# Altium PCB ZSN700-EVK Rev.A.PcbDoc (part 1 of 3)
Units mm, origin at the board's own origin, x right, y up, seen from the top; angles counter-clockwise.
Board outline 122.05 x 75.06 mm, 2 copper layers (Top Layer, Bottom Layer), stack 0 mm thick; 172 components, 135 nets, 573 pads, 599 vias.
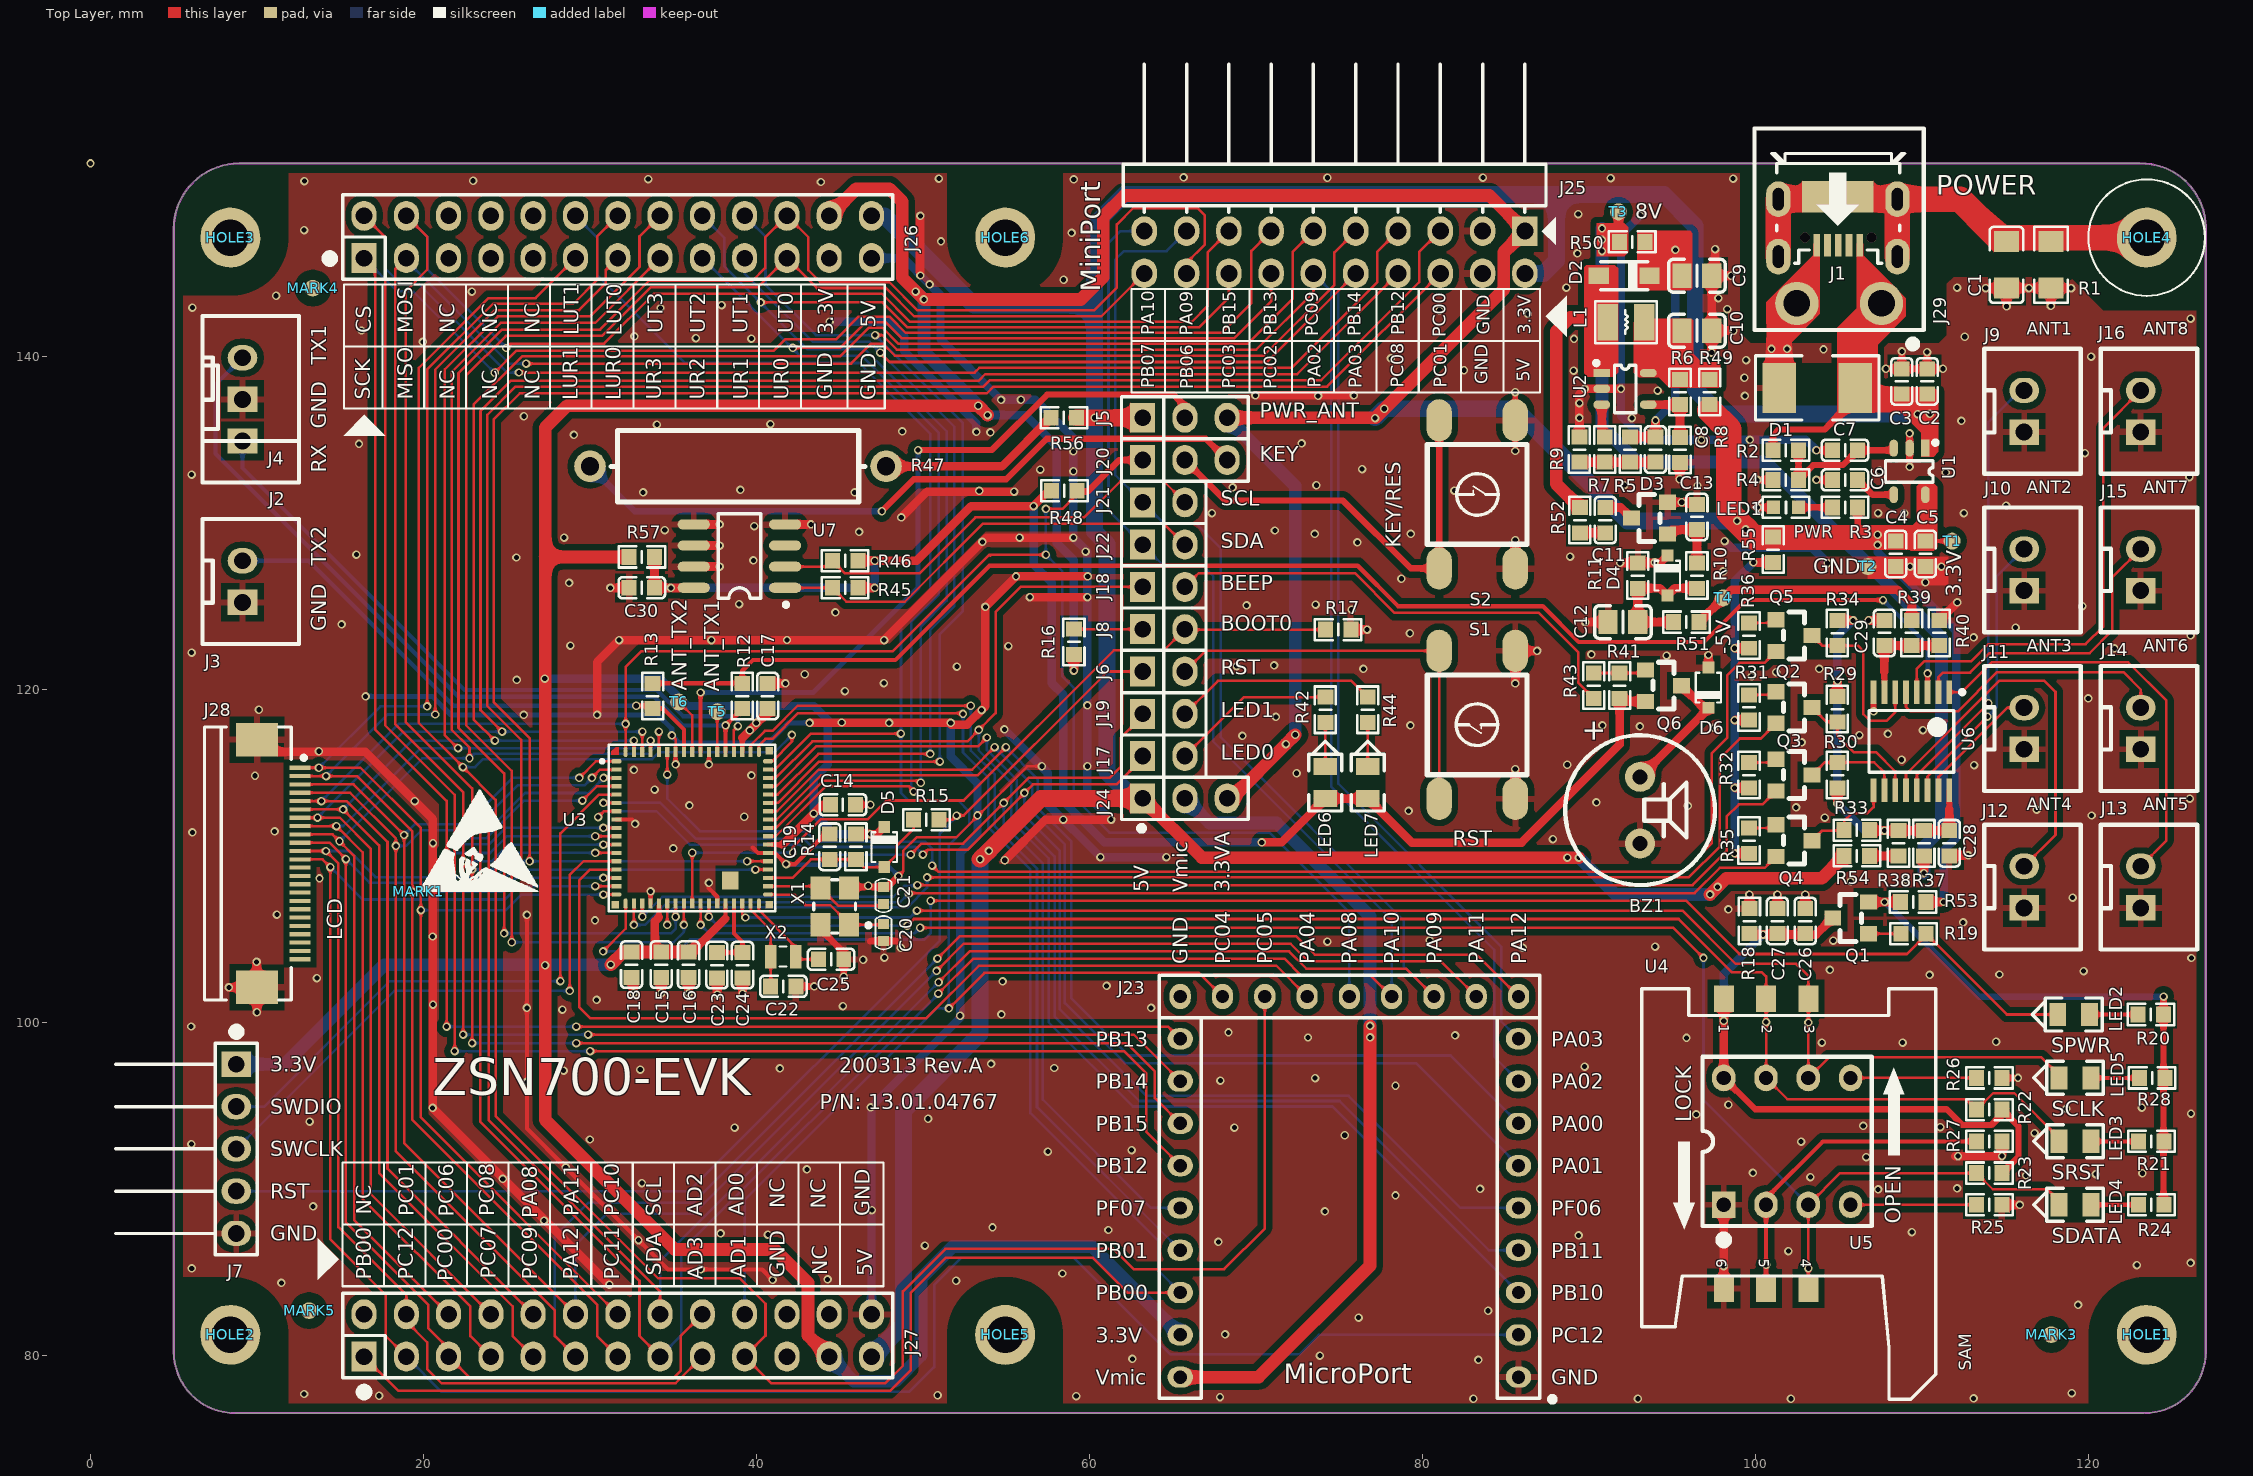
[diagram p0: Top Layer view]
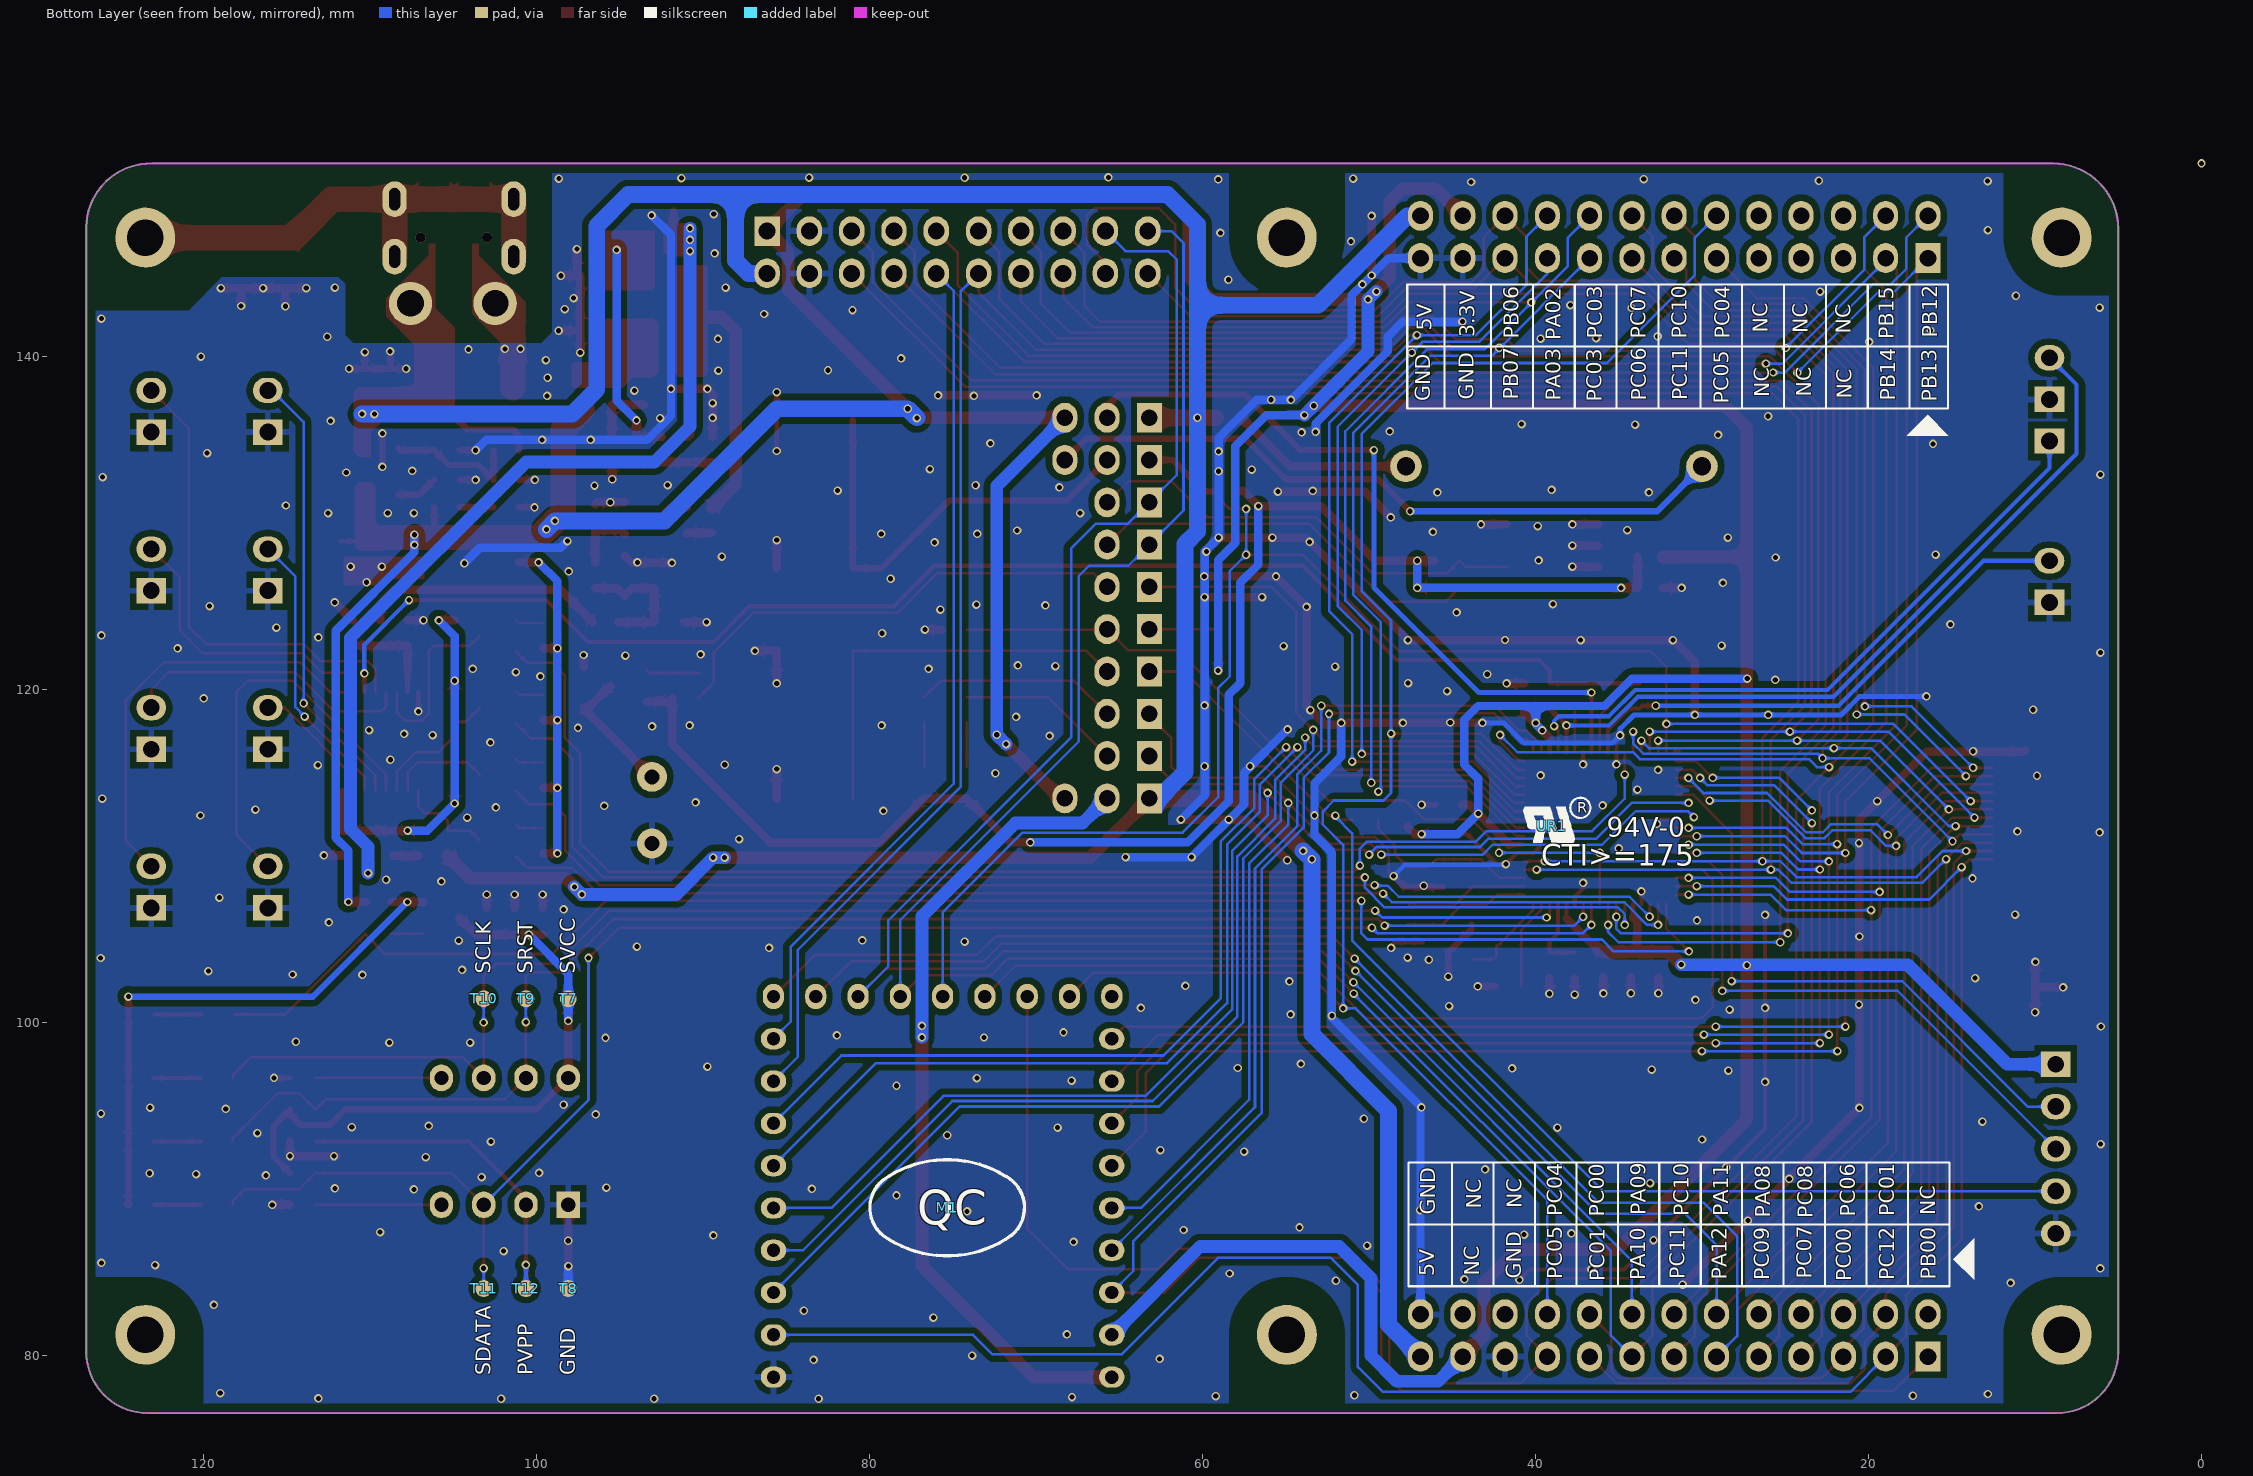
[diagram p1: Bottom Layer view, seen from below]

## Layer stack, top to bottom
Top Layer: signal copper (thickness not stored)
Bottom Layer: signal copper (thickness not stored)

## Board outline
5,80.24 ccw(c8.683,80.24) 8.683,76.557 123.364,76.557 ccw(c123.364,80.24) 127.047,80.24 127.047,147.804 ccw(c123.174,147.74) 123.11,151.614 8.937,151.614 ccw(c8.937,147.677) 5,147.677

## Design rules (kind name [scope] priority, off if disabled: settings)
Clearance Clearance_Keepout [OnLayer('Keep-Out Layer')] p1: gap=0.508
Clearance Clearance_Wave [OnLayer('Bottom Layer') and IsSMTPin vs IsPadHoleValid>   (  HasFootprint('PAD-40') or  HasFootprint('HOLE-3.2') or  HasFootprint('HOLE-3.2 - Screw') or   HasFootprint('DIP762W62P254L1016H500Q8P') or   HasFootprint('Mou Hole-300D450W310H-SMD') or    HasFootprint('AW6748') or HasFootprint('IDCS80P500W-20X2-F')  )] p2: gap=4
Clearance Clearance_Via2Via [IsVia vs IsVia] p3: gap=0.152
Clearance Clearance_Poly2All [InPoly] p4: gap=0.381
Clearance Clearance_TP [HasFootprint('PAD-40') vs HasFootprint('PAD-40')] p5: gap=1.27
Clearance [All] p6: gap=0.127
ComponentClearance [All] p1 off: gap=0.254 collisioncheckmode=3 verticalgap=0.254 showdistances=FALSE
DiffPairsRouting [All] p1: maxlimit=0.203 minlimit=0.203 mostfreqgap=0.203 toplayer_minwidth=0.13 toplayer_maxwidth=0.13 toplayer_prefwidth=0.13 bottomlayer_minwidth=0.13 bottomlayer_maxwidth=0.13 bottomlayer_prefwidth=0.13 maxuncoupledlength=12.7
Height [All] p1 off: minheight=0 maxheight=25.4 prefheight=12.7
HoleSize [All] p1: absolutevalues=TRUE maxlimit=25.4 minlimit=0.025 maxpercent=80.000 minpercent=20.000
HoleToHoleClearance [All vs All > InPadClass('New Class')] p1: gap=0.254 allowstackedmicrovias=TRUE
MinimumSolderMaskSliver [All] p1 off: minsoldermaskwidth=0.102
PasteMaskExpansion [All] p1 off: expansion=0
PlaneClearance PlaneClearance_Full [IsVia] p1: clearance=0.229
PlaneClearance [All] p2: clearance=0.508
PlaneConnect PlaneConnect_Full [IsVia] p1: planeconnectstyle=Direct reliefexpansion=0.508 reliefentries=4 reliefconductorwidth=0.254 reliefairgap=0.254
PlaneConnect [All] p2: planeconnectstyle=Relief reliefexpansion=0.254 reliefentries=4 reliefconductorwidth=0.381 reliefairgap=0.254
PolygonConnect PolygonConnect_SMDHole [HasFootprint('Mou Hole-300D450W310H-SMD') or HasFootprint('Mou Hole-373D600H-SMD')] p1: connectstyle=Relief reliefconductorwidth=2.032 reliefentries=4 polygonreliefangle="45 Angle" airgapwidth=0.508
PolygonConnect PolygonConnect_Full [IsVia or   HasFootprint('PAD-40') or  HasFootprint('PAD-35/50') or  HasFootprint('HOLE-3.2') or   HasFootprint('HOLE-3.2 - Screw')] p2: connectstyle=Direct reliefconductorwidth=0.254 reliefentries=4 polygonreliefangle="90 Angle" airgapwidth=0.254
PolygonConnect [All] p3: connectstyle=Relief reliefconductorwidth=0.381 reliefentries=4 polygonreliefangle="90 Angle" airgapwidth=0.381
RoutingVias [All] p1: holewidth=0.305 width=0.508 viastyle="Through Hole" minholewidth=0.305 minwidth=0.508 maxholewidth=0.305 maxwidth=0.508
SilkToBoardRegionClearance [All] p1 off:
SilkToSilkClearance [All] p1 off: silktosilkclearance=0.051
SilkToSolderMaskClearance [IsPad] p1 off: minsilkscreentomaskgap=0.051 clearancetoexposedcopper=TRUE
SolderMaskExpansion [All] p1 off: expansion=0.102
UnpouredPolygon [All] p1: allowunpoured=FALSE
Width [All] p1: maxlimit=2.54 minlimit=0.127 preferedwidth=0.127
17 further rules are at their usual default settings.

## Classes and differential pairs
pad class "New Class": J2-2 J2-3 J4-1 J4-2
differential pair class NET: NET_RXD NET_TXD
differential pair class USB: USB0 USB0_D USB0_H USB1 USB1_D USB1_H
differential pair class big: RX TX

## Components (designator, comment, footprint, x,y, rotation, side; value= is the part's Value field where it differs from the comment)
BZ1 "BUZZER2" BUZZ-4/9 93.069,112.771 r270 top locked
C1 "CC1206KKX7RDBB102,102" 1206C 115.082,145.518 r270 top
C2 "10μF,6.3V" 0603C 110.316,138.518 r270 top
C3 "C1608X7R1H104KT000N，104" 0603C 108.792,138.518 r270 top
C4 "C1608X7R1H104KT000N，104" 0603C 108.429,128.162 r90 top
C5 "10μF,6.3V" 0603C 110.207,128.162 r90 top
C6 "103,±10%" 0603C 105.381,132.607 r0 top
C7 "103,±10%" 0603C 105.381,134.385 r0 top
C8 "200P" 0603C 93.998,134.428 r270 top
C9 "475,4.7μF" 0805C 96.487,144.868 r0 top
C10 "10μF,±10%" 0805C 96.487,141.566 r0 top
C11 "0.1μF" 0603C 90.979,130.192 r90 top
C12 "10μF,±10%" 0805C 92.042,124.065 r180 top
C13 "0.1μF" 0603C 96.487,130.38 r270 top
C14 "0.1uF,50V,0603" 0603C 45.196,113.096 r0 top
C15 "0.1uF,50V,0603" 0603C 34.277,103.495 r270 top
C16 "0.1uF,50V,0603" 0603C 35.923,103.49 r270 top
C17 "0.1uF,50V,0603" 0603C 40.671,119.624 r90 top
C18 "4.7uF" 0603C 32.499,103.495 r270 top
C19 "0.1uF,50V,0603" 0603C 44.399,110.57 r90 top
C20 "6.2pF,±0.25PF" 0402C 47.631,105.41 r90 top
C21 "6.2pF,±0.25PF" 0402C 47.631,107.645 r90 top
C22 "15pF,50V,0603" 0603C 41.617,102.185 r0 top
C23 "0.1uF,50V,0603" 0603C 37.624,103.464 r270 top
C24 "16V,TDK,1uF" 0603C 39.163,103.464 r270 top
C25 "15pF,50V,0603" 0603C 44.481,103.81 r0 top
C26 "104" 0603C 102.993,106.111 r90 top
C27 "104" 0603C 101.316,106.111 r90 top
C28 "104" 0603C 111.643,110.781 r270 top
C29 "104" 0603C 107.743,123.412 r90 top
C30 "C1608X7R1H104KT000N，104" 0603C 33.112,126.124 r180 top
D1 "SMBJ6.5CA" SOD-1812 103.712,138.137 r180 top
D2 "MBR0520LT1G" SOD-123 92.118,144.868 r0 top
D3 "BAV99" SOT-23 93.63,130.314 r180 top
D4 "BZX384-C5V1,SOD-323" SOD-323 94.709,126.859 r90 top
D5 "1N4148" SOD-323 47.676,110.556 r90 top
D6 "DIODE1" SOD-323 97.177,120.131 r270 top
HOLE1 "" HOLE-2.2 123.5,81.258 r110 top locked
HOLE2 "" HOLE-2.2 8.4,81.258 r70 top locked
HOLE3 "" HOLE-2.2 8.4,147.158 r350 top locked
HOLE4 "" HOLE-2.2 123.5,147.158 r190 top locked
HOLE5 "" HOLE-2.2 54.94,81.258 r90 top locked
HOLE6 "" HOLE-2.2 54.94,147.158 r350 top locked
J1 "ST-USB-002B-1,SMT" MICROUSB-ST-USB-002B-1 104.949,147.814 r180 top locked
J2 "2.5-3T,180°" CON250P580W100D50S-3DIP 9.63,137.442 r90 top
J3 "2.5-2T,180°" CON250P580W100D50S-2DIP 9.63,126.5 r90 top
J4 "2.5-2T,180°" CON250P580W100D50S-2DIP 9.63,138.692 r90 top
J5 "PWR_ANT" SIP-3-2.54 65.731,136.338 r0 top
J6 "CON2" SIP-2-2.54 64.461,121.098 r0 top
J7 "SWD" SIP-5-2.54-6.0-R90 8.755,92.426 r270 top
J8 "CON2" SIP-2-2.54 64.461,123.638 r0 top
J9 "ANT1" CON250P580W100D50S-2DIP 116.643,136.727 r90 top
J10 "ANT2" CON250P580W100D50S-2DIP 116.643,127.201 r90 top
J11 "ANT3" CON250P580W100D50S-2DIP 116.643,117.675 r90 top
J12 "ANT4" CON250P580W100D50S-2DIP 116.643,108.15 r90 top
J13 "ANT5" CON250P580W100D50S-2DIP 123.643,108.15 r90 top
J14 "ANT6" CON250P580W100D50S-2DIP 123.643,117.675 r90 top
J15 "ANT7" CON250P580W100D50S-2DIP 123.643,127.201 r90 top
J16 "ANT8" CON250P580W100D50S-2DIP 123.643,136.727 r90 top
J17 "LED0" SIP-2-2.54 64.461,116.018 r0 top
J18 "BEEP" SIP-2-2.54 64.461,126.178 r0 top
J19 "LED1" SIP-2-2.54 64.461,118.558 r0 top
J20 "KEY" SIP-3-2.54 65.731,133.798 r0 top
J21 "SCL" SIP-2-2.54 64.461,131.258 r0 top
J22 "SDA" SIP-2-2.54 64.461,128.718 r0 top
J23 "3X7Inter" "SIP-27 2.54C" 88.312,81.383 r180 top locked
J24 "" SIP-3-2.54 65.731,113.478 r0 top
J25 "HEADER 10X2" IDC-20-2.54-R90 74.723,146.28 r180 top locked
J26 "HEADER 13X2" IDC-26-2.54 31.67,147.196 r0 top locked
J27 "HEADER 13X2" IDC-26-2.54 31.67,81.22 r0 top locked
J28 "0.5FFC-24PIN" FFCF0.5-24P-R0-A 11.288,109.566 r270 top
J29 "2EDGR/2EDGK-5.08-02P-14-00AH" CON508P1210W160D445S-2RA 105.029,147.656 r180 top locked
L1 "MPH252012C2R2MT,2.2μH" INDC2520X10N 92.227,142.074 r180 top
LED1 "0603QRC,红色" LED-0603 101.837,130.956 r180 top
LED2 "0805QGC,绿色" LED-0805 119.118,100.496 r180 top
LED3 "0805QGC,绿色" LED-0805 119.194,92.876 r180 top
LED4 "0805QGC,绿色" LED-0805 119.194,89.066 r180 top
LED5 "0805QGC,绿色" LED-0805 119.194,96.686 r180 top
LED6 "LED0" LED-0805 74.172,114.424 r90 top
LED7 "LED1" LED-0805 76.712,114.424 r90 top
M1 "ZY QC" ZY_QC 75.337,88.889 r180 bottom
MARK1 "ESD-MARK" ZY_ESD-7 19.689,107.86 r0 top
MARK3 "MARKER" MARKER-C-1.0M 117.776,81.268 r90 top
MARK4 "MARKER" MARKER-C-1.0M 13.355,144.121 r90 top
MARK5 "MARKER" MARKER-C-1.0M 13.128,82.708 r90 top
Q1 "PNP-1" SOT-23 105.723,106.299 r180 top
Q2 "SS8050LT(1.5A),SOT-23" SOT-23 102.32,118.938 r0 top
Q3 "SS8050LT(1.5A),SOT-23" SOT-23 102.32,114.874 r0 top
Q4 "SS8050LT(1.5A),SOT-23" SOT-23 102.32,110.937 r0 top
Q5 "SS8050LT(1.5A),SOT-23" SOT-23 102.32,123.256 r0 top
Q6 "PNP-1" SOT-23 94.472,120.245 r0 top
R1 "1MΩ,1206" 1206R 117.749,145.518 r90 top
R2 "20KΩ" 0603R 101.825,134.385 r0 top
R3 "2KΩ" 0603R 105.381,130.956 r0 top
R4 "15KΩ" 0603R 101.825,132.607 r180 top
R5 "120KΩ,±1%" 0603R 92.474,134.428 r90 top
R6 "30KΩ" 0603R 95.471,137.883 r90 top
R7 "100KΩ" 0603R 90.95,134.428 r90 top
R8 "22K,±1%" 0603R 95.471,134.403 r90 top
R9 "22K,±1%" 0603R 89.426,134.428 r270 top
R10 "470Ω" 0603R 96.487,126.859 r270 top
R11 "100KΩ" 0603R 92.931,126.859 r270 top
R12 "0Ω" 0603R 39.147,119.624 r90 top
R13 "0Ω" 0603R 33.762,119.624 r90 top
R14 "10KΩ,±1%" 0603R 45.974,110.57 r90 top
R15 "0Ω" 0603R 50.202,112.193 r0 top
R16 "1KΩ,±0.5%,0603" 0603R 59.067,122.876 r270 top
R17 "10KΩ,±1%" 0603R 74.936,123.612 r180 top
R18 "10KΩ,±1%" 0603R 99.64,106.111 r90 top
R19 "2KΩ" 0603R 109.492,105.349 r180 top
R20 "2KΩ" 0603R 123.75,100.496 r0 top
R21 "2KΩ" 0603R 123.784,92.876 r0 top
R22 "10KΩ,±1%" 0603R 114.046,94.781 r0 top
R23 "10KΩ,±1%" 0603R 114.046,90.971 r0 top
R24 "2KΩ" 0603R 123.784,89.066 r0 top
R25 "2KΩ" 0603R 114.046,89.066 r180 top
R26 "2KΩ" 0603R 114.046,96.686 r180 top
R27 "2KΩ" 0603R 114.046,92.876 r180 top
R28 "2KΩ" 0603R 123.827,96.686 r0 top
R29 "100KΩ" 0603R 104.923,118.836 r90 top
R30 "100KΩ" 0603R 104.923,114.874 r270 top
R31 "100KΩ" 0603R 99.615,118.938 r270 top
R32 "100KΩ" 0603R 99.615,114.874 r270 top
R33 "100KΩ" 0603R 106.094,111.572 r0 top
R34 "100KΩ" 0603R 104.923,123.408 r90 top
R35 "100KΩ" 0603R 99.615,110.937 r270 top
R36 "100KΩ" 0603R 99.615,123.256 r270 top
R37 "0Ω" 0603R 110.119,110.781 r90 top
R38 "0Ω" 0603R 108.595,110.781 r90 top
R39 "0Ω" 0603R 109.394,123.412 r270 top
R40 "0Ω" 0603R 111.045,123.412 r270 top
R41 "10KΩ,±1%" 0603R 91.843,120.245 r270 top
R42 "1.5KΩ" 0603R 74.172,118.801 r90 top
R43 "1.5KΩ" 0603R 90.293,120.245 r90 top
R44 "1.5KΩ" 0603R 76.712,118.801 r90 top
R45 "10KΩ,±1%" 0603R 45.33,126.124 r0 top
R46 "10KΩ,±1%" 0603R 45.33,127.75 r0 top
R47 "20Ω,±5%" RESAD1778W80L1450D430P 38.893,133.417 r180 top
R48 "4.7KΩ" 0603R 58.492,131.958 r180 top
R49 "0Ω" 0603R 97.249,137.883 r90 top
R50 "0Ω" 0603R 92.601,146.9 r180 top
R51 "0Ω" 0603R 95.852,124.065 r0 top
R52 "0Ω" 0603R 89.455,130.192 r270 top
R53 "0Ω" 0603R 109.47,107.254 r180 top
R54 "0Ω" 0603R 106.094,110.023 r0 top
R55 "0Ω" 0603R 101.063,128.416 r270 top
R56 "0Ω" 0603R 58.467,136.338 r180 top
R57 "0Ω" 0603R 33.112,127.978 r0 top
S1 "6×6×5.0mm" KEY-6S 83.29,117.895 r90 top
S2 "KEY/RES" KEY-6S 83.29,131.738 r270 top
T1 "3.3V" PAD-40 111.815,128.928 r270 top
T2 "GND" PAD-40 106.76,127.404 r270 top
T3 "8V" PAD-40 91.775,148.703 r0 top
T4 "-5V" PAD-40 98.067,125.518 r180 top
T5 "ANT-TX1" PAD-40 37.639,118.685 r0 top
T6 "ANT-TX2" PAD-40 35.328,119.27 r0 top
T7 "TEST-DOT" PAD-40 98.098,101.437 r180 bottom
T8 "TEST-DOT" PAD-40 98.098,84.037 r180 bottom
T9 "TEST-DOT" PAD-40 100.638,101.437 r180 bottom
T10 "TEST-DOT" PAD-40 103.178,101.437 r180 bottom
T11 "TEST-DOT" PAD-40 103.178,84.037 r180 bottom
T12 "TEST-DOT" PAD-40 100.638,84.037 r180 bottom
U1 "ZL6205A33TS5,SOT-23-5" SOT-23-5 109.257,133.115 r270 top
U2 "MP1541DJ" SOT-23-5 92.169,138.076 r0 top
U3 "ZSN700 S0.00" "ZSN700 S0.00" 36.14,111.702 r0 top locked
U4 "掀盖式1.8高SIM卡座" SIM-CARD-24.65X17.65-6P 101.998,91.887 r0 top locked
U5 "HEADER 4X2R" DIP762W62P254L1016H500Q8P 101.905,92.876 r90 top locked
U6 "HEF4051BTT" SOP65P640X110-16N 109.368,116.906 r270 top locked
U7 "LM75B" SOIC127P600X175-8N 38.979,128.029 r180 top
UR1 "UR" ZY_UR-3X2 39.036,111.816 r180 bottom
X1 "JYD3A1C7G6-10-12.000,12.0000MHz" OSCCC250X320X80-4N 44.699,106.992 r90 top
X2 "SC-20S,32.768kHz" XTAL205X120X60-2N 41.601,103.973 r180 top

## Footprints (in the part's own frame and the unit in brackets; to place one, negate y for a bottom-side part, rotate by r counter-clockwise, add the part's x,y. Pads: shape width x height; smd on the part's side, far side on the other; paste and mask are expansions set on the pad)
0402C [mm]
  rect 0.6x0.65 smd mask+0.025: 1(-0.508,0) 2(0.508,0)
  silkscreen extent -1.01,-0.48 1.01,0.48, body extent -0.51,-0.23 0.49,0.27, height 0.5
0603C [mm]
  rect 0.9x0.95 smd: 1(-0.762,0) 2(0.762,0)
  silkscreen extent -1.4,-0.64 1.4,0.64, body extent -0.79,-0.38 0.81,0.42, height 0.3
0603R [mm]
  rect 0.9x0.95 smd: 1(-0.762,0) 2(0.762,0)
  silkscreen extent -1.4,-0.64 1.4,0.64, body extent -0.8,-0.4 0.8,0.4, height 0.3
0805C [mm]
  rect 1.15x1.45 smd: 1(-0.889,0) 2(0.889,0)
  silkscreen extent -1.7,-0.99 1.7,0.99, body extent -1,-0.63 1,0.63, height 0.78
1206C [mil] "元件 长X宽=120X60mil"
  rect 50x60 smd: 1(-55,0) 2(55,0)
  silkscreen extent -90,-40 90,40, body extent -62,-32 64,31, height 39
1206R [mil] "元件 长X宽=120X60mil"
  rect 50x60 smd: 1(-55,0) 2(55,0)
  silkscreen extent -90,-40 90,40, body extent -63,-31 63,31, height 24
BUZZ-4/9 [mm]
  round 1.8 hole 0.9: 1(-2,0) 2(2,0)
  silkscreen extent -4.5,-4.5 4.5,4.5
CON250P580W100D50S-2DIP [mil]
  rect 60x70 hole 40: 1(-49.21,19.69)
  oval 60x70 hole 40: 2(49.21,19.69)
  silkscreen extent -148,-114 148,114, body extent -147,-120 148,116, height 276
CON250P580W100D50S-3DIP [mil]
  rect 60x70 hole 40: 1(-98.43,19.69)
  oval 60x70 hole 40: 2(0,19.69) 3(98.43,19.69)
  silkscreen extent -197,-114 197,114, body extent -197,-119 197,117, height 276
CON508P1210W160D445S-2RA [mm]
  round 2.6 hole 1.6: 1(-2.54,4.45) 2(2.54,4.45)
  silkscreen extent -5.08,-6.05 5.08,7.09
DIP762W62P254L1016H500Q8P [mm]
  rect 1.6x1.4 hole 0.85: 1(-3.81,3.81)
  oval 1.6x1.4 hole 0.85: 2(-3.81,1.27) 3(-3.81,-1.27) 4(-3.81,-3.81) 5(3.81,-3.81) 6(3.81,-1.27) 7(3.81,1.27) 8(3.81,3.81)
  silkscreen extent -6.17,-5.08 5.08,5.08
FFCF0.5-24P-R0-A [mm]
  rect 0.25x1.25 smd: 1(-5.75,1.288) 2(-5.25,1.288) 3(-4.75,1.288) 4(-4.25,1.288) 5(-3.75,1.288) 6(-3.25,1.288) 7(-2.75,1.288) 8(-2.25,1.288) 9(-1.75,1.288) 10(-1.25,1.288) 11(-0.75,1.288) 12(-0.25,1.288) 13(0.25,1.288) 14(0.75,1.288) 15(1.25,1.288) 16(1.75,1.288) 17(2.25,1.288) 18(2.75,1.288) 19(3.25,1.288) 20(3.75,1.288) 21(4.25,1.288) 22(4.75,1.288) 23(5.25,1.288) 24(5.75,1.288)
  rect 2x2.5 smd: 25(-7.44,-1.288) 26(7.44,-1.288)
  Top Layer pour cut-out: -6.1,2.1 -6.1,0.5 6.1,0.5 6.1,2.1
  silkscreen extent -8.2,-4.44 8.2,1.65, body extent -8.25,-4.44 8.25,0.76, height 2
HOLE-2.2 [mm]
  round 3.6 hole 2.2: 1(0,0)
IDC-20-2.54-R90 [mil] "Connector; Header; 10x2 Position"
  rect 60x70 hole 40: 1(-450,-50)
  oval 60x70 hole 40: 2(-450,50) 3(-350,-50) 4(-350,50) 5(-250,-50) 6(-250,50) 7(-150,-50) 8(-150,50) 9(-50,-50) 10(-50,50) 11(50,-50) 12(50,50) 13(150,-50) 14(150,50) 15(250,-50) 16(250,50) 17(350,-50) 18(350,50) 19(450,-50) 20(450,50)
  silkscreen extent -522,-444 500,-17
IDC-26-2.54 [mm]
  rect 1.5x1.8 hole 1: 1(-15.24,-1.27)
  oval 1.5x1.8 hole 1: 2(-15.24,1.27) 3(-12.7,-1.27) 4(-12.7,1.27) 5(-10.16,-1.27) 6(-10.16,1.27) 7(-7.62,-1.27) 8(-7.62,1.27) 9(-5.08,-1.27) 10(-5.08,1.27) 11(-2.54,-1.27) 12(-2.54,1.27) 13(0,-1.27) 14(0,1.27) 15(2.54,-1.27) 16(2.54,1.27) 17(5.08,-1.27) 18(5.08,1.27) 19(7.62,-1.27) 20(7.62,1.27) 21(10.16,-1.27) 22(10.16,1.27) 23(12.7,-1.27) 24(12.7,1.27) 25(15.24,-1.27) 26(15.24,1.27)
  silkscreen extent -17.55,-2.54 16.51,2.54, body extent -16.51,-2.54 16.51,2.54, height 7.58
INDC2520X10N [mm] "Chip Inductor, 2-Leads, Body 2.50x2.00mm, IPC Medium Density"
  rect 1.23x2.22 smd: 1(-1.085,0) 2(1.085,0)
  Top Layer pour cut-out: -0.475,-1.225 -0.475,1.225 0.475,1.225 0.475,-1.225
  silkscreen extent -1.85,-1.27 1.85,1.27, body extent -1.35,-1.1 1.35,1.1, height 1
KEY-6S [mil]
  oval 100x60 smd: 1(-175,90) 2(-175,-90) 3(175,-90) 4(175,90)
  silkscreen extent -118,-118 118,118, body extent -201,-122 201,122, height 268
LED-0603 [mm] "20100324  贴片0603LED   LSB"
  rect 0.8x0.8 smd: 1(-0.75,0) 2(0.75,0)
  silkscreen extent -1.4,-0.64 1.93,0.64, body extent -0.8,-0.4 0.8,0.4, height 0.4
LED-0805 [mm] "170907内距改0.9mm"
  rect 1.014x1.4 smd: 1(-0.957,0) 2(0.957,0)
  silkscreen extent -1.7,-0.99 2.49,0.99, body extent -1,-0.64 1,0.64, height 1.1
MARKER-C-1.0M [mm]
  round 1 smd paste-1.016 mask+0.5: 0(0,0)
  Top Layer pour cut-out: -1.1,0 -1.016,-0.421 -0.778,-0.778 -0.421,-1.016 0,-1.1 0,-1.1 0.421,-1.016 0.778,-0.778 1.016,-0.421 1.1,0 1.1,0 1.016,0.421 0.778,0.778 0.421,1.016 0,1.1 0,1.1 -0.421,1.016 -0.778,0.778 -1.016,0.421 -1.1,0
MICROUSB-ST-USB-002B-1 [mm]
  oval 1.45x2.15 on Top Paste: 0(-3.575,-1.65) 0(-3.575,1.8) 0(3.575,-1.65) 0(3.575,1.8)
  round 0.6 hole 0.6 unplated: 0(-2.025,0.65) 0(1.975,0.65)
  rect 0.4x1.35 smd: 1(-1.325,1.115) 2(-0.675,1.115) 3(-0.025,1.115) 4(0.625,1.115) 5(1.275,1.115)
  oval 1.45x2.15 hole 0.65 slot 1.35 at 90 deg: 6(-3.575,1.8) 7(3.575,1.8) 8(-3.575,-1.65) 9(3.575,-1.65)
  rect 1.9x1.9 smd: 10(-1.2,-1.8) 11(1.2,-1.8)
  silkscreen extent -4.02,-4.4 3.98,2.2
OSCCC250X320X80-4N [mm]
  rect 1.4x1.2 smd: 1(-1.1,-0.85) 2(1.1,-0.85) 3(1.1,0.85) 4(-1.1,0.85)
  silkscreen extent -1.6,-2.16 1.6,1.25
PAD-40 [mil]
  round 40 smd paste-43.31: 1(0,0)
RESAD1778W80L1450D430P [mm]
  round 1.9 hole 1.1: 1(-8.89,0) 2(8.89,0)
  silkscreen extent -7.62,-2.15 7.62,2.15
SIM-CARD-24.65X17.65-6P [mm]
  rect 1.2x1.6 smd mask+0.051: 1(-3.9,9.55) 2(-1.36,9.55) 3(1.18,9.55) 4(1.18,-7.85) 5(-1.36,-7.85) 6(-3.9,-7.85)
  silkscreen extent -8.82,-14.5 8.82,10.15
SIP-2-2.54 [mm]
  rect 1.5x1.8 hole 1: 1(-1.27,0)
  oval 1.5x1.8 hole 1: 2(1.27,0)
  silkscreen extent -2.54,-1.27 2.54,1.27, body extent -2.54,-1.27 2.54,1.27, height 7.58
SIP-3-2.54 [mm]
  rect 1.5x1.8 hole 1: 1(-2.54,0)
  oval 1.5x1.8 hole 1: 2(0,0) 3(2.54,0)
  silkscreen extent -3.81,-1.27 3.81,1.27, body extent -3.81,-1.27 3.81,1.27, height 7.58
SIP-5-2.54-6.0-R90 [mil] "引脚伸出部分为6.0mm"
  rect 60x70 hole 40: 1(-200,0)
  oval 60x70 hole 40: 2(-100,0) 3(0,0) 4(100,0) 5(200,0)
  silkscreen extent -286,-285 250,49
"SIP-27 2.54C" [mil]
  oval 60x50 hole 31.5: 1(100,105) 2(100,5) 3(100,-95) 4(100,-195) 5(100,-295) 6(100,-395) 7(100,-495) 8(100,-595) 9(100,-695) 19(900,-695) 20(900,-595) 21(900,-495) 22(900,-395) 23(900,-295) 24(900,-195) 25(900,-95) 26(900,5) 27(900,105)
  oval 50x60 hole 31.5: 10(100,-795) 11(200,-795) 12(300,-795) 13(400,-795) 14(500,-795) 15(600,-795) 16(700,-795) 17(800,-795) 18(900,-795)
  silkscreen extent 15,-845 950,162
SOD-123 [mm]
  rect 1.22x1 smd: 1(-1.524,0) 2(1.524,0)
  silkscreen extent -1.42,-0.85 1.43,0.85, body extent -1.85,-0.81 1.85,0.79, height 1.2
SOD-323 [mil]
  rect 28x28 smd: 1(-47.5,0) 2(47.5,0)
  silkscreen extent -35,-30 35,30, body extent -51,-26 51,25, height 39
SOD-1812 [mm]
  rect 2x3 smd: 1(-2.286,0) 2(2.286,0)
  Top Layer pour cut-out: -1.27,1.499 -1.27,-1.499 1.245,-1.499 1.245,1.499
  silkscreen extent -3.71,-1.93 3.71,1.93
SOIC127P600X175-8N [mil]
  oval 76.06x24 smd: 1(-108.03,75) 2(-108.03,25) 3(-108.03,-25) 4(-108.03,-75) 5(108.03,-75) 6(108.03,-25) 7(108.03,25) 8(108.03,75)
  silkscreen extent -115,-100 50,120, body extent -118,-96 118,97, height 61
SOP65P640X110-16N [mm] "TSOP, 16-Leads, Body 5.00x4.40mm, Pitch 0.65mm, IPC Medium Density"
  rect 1.4x0.35 smd: 1(-2.95,2.275) 2(-2.95,1.625) 3(-2.95,0.975) 4(-2.95,0.325) 5(-2.95,-0.325) 6(-2.95,-0.975) 7(-2.95,-1.625) 8(-2.95,-2.275) 9(2.95,-2.275) 10(2.95,-1.625) 11(2.95,-0.975) 12(2.95,-0.325) 13(2.95,0.325) 14(2.95,0.975) 15(2.95,1.625) 16(2.95,2.275)
  silkscreen extent -3.07,-2.55 1.85,3.18, body extent -2.25,-2.55 2.25,2.55, height 1.1
SOT-23 [mil]
  rect 40x36 smd: 1(-42.5,37.4) 2(-42.5,-37.4) 3(42.5,0)
  silkscreen extent -25,-56 25,56, body extent -47,-57 50,58, height 39
SOT-23-5 [mil]
  rect 40x20 smd: 1(-55,37.4)
  oval 40x20 smd: 2(-55,0) 3(-55,-37.4) 4(55,-37.4) 5(55,37.4)
  silkscreen extent -73,-57 26,66, body extent -55,-57 55,57, height 43
XTAL205X120X60-2N [mm]
  rect 0.7x1.4 smd: 1(-0.75,0) 2(0.75,0)
  silkscreen extent -0.2,-0.6 0.2,0.6
"ZSN700 S0.00" [mm] "ZLGLIB_"
  oct 0.6x0.25 smd mask+0.051: 1(-4.55,4) 17(-4.55,-4) 35(4.55,-4) 51(4.55,4)
  rect 0.6x0.25 smd mask+0.051: 2(-4.55,3.5) 3(-4.55,3) 4(-4.55,2.5) 5(-4.55,2) 6(-4.55,1.5) 7(-4.55,1) 8(-4.55,0.5) 9(-4.55,0) 10(-4.55,-0.5) 11(-4.55,-1) 12(-4.55,-1.5) 13(-4.55,-2) 14(-4.55,-2.5) 15(-4.55,-3) 16(-4.55,-3.5) 36(4.55,-3.5) 37(4.55,-3) 38(4.55,-2.5) 39(4.55,-2) 40(4.55,-1.5) 41(4.55,-1) 42(4.55,-0.5) 43(4.55,0) 44(4.55,0.5) 45(4.55,1) 46(4.55,1.5) 47(4.55,2) 48(4.55,2.5) 49(4.55,3) 50(4.55,3.5)
  oct 0.25x0.6 smd mask+0.051: 18(-3.997,-4.55) 34(4.003,-4.55) 52(4.003,4.55) 68(-3.997,4.55)
  rect 0.25x0.6 smd mask+0.051: 19(-3.497,-4.55) 20(-2.997,-4.55) 21(-2.497,-4.55) 22(-1.997,-4.55) 23(-1.497,-4.55) 24(-0.997,-4.55) 25(-0.497,-4.55) 26(0.003,-4.55) 27(0.503,-4.55) 28(1.003,-4.55) 29(1.503,-4.55) 30(2.003,-4.55) 31(2.503,-4.55) 32(3.003,-4.55) 33(3.503,-4.55) 53(3.503,4.55) 54(3.003,4.55) 55(2.503,4.55) 56(2.003,4.55) 57(1.503,4.55) 58(1.003,4.55) 59(0.503,4.55) 60(0.003,4.55) 61(-0.497,4.55) 62(-0.997,4.55) 63(-1.497,4.55) 64(-1.997,4.55) 65(-2.497,4.55) 66(-2.997,4.55) 67(-3.497,4.55)
  rect 0.45x0.45 smd mask+0.051: ""(-4.625,-4.625) ""(4.625,-4.625) ""(4.625,4.625)
  rect 1x1.07 smd: ""(2.28,-3.16)
  Top Layer region: -4.85,4.4 -4.85,4.6 -4.6,4.85 -4.4,4.85 -4.4,4.4
  silkscreen extent -5.51,-5 5,5
ZY_ESD-7 [mm]
  silkscreen extent 0.03,0.03 7.21,6.15
ZY_QC [mm]
  silkscreen extent -4.64,-2.89 4.64,2.89
ZY_UR-3X2 [mm]
  silkscreen extent -1.7,-1.02 2.33,1.7

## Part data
BZ1: library part 1.06.09.0016, "Buzzer有极性"
C1: library part 1.02.03.0003, "CC1206KKX7RDBB102,102,±10%,2KV,X7R,1206,YAGEO,RoHS"
C2 C5: library part 1.02.01.0065, "10μF,6.3V,X5R,GRM188R60J106M****,0603,Murata,RoHS"
C3 C4 C30: library part 1.02.01.0072, "C1608X7R1H104KT000N，104，±10%，50V，X7R,TDK,0603,RoHS"
C6 C7: library part 1.02.01.0090, "103,±10%,50V,X7R,0603,GCM188R71H103KA15D,0603,muRata,ROHS"
C8: library part 1.02.01.0015, "GRM1885C1H201JA01D,200P,±5%,50V,COG,0603,muRata,RoHS"
C9: library part 1.02.02.0086, "GRM21BR71C475KA73L,475,4.7μF,±10%,16V,X7R,0805,murata,RoHS"
C10 C12: library part 1.02.02.0117, "10μF,±10%,10V,X7R,GRM21BR71A106KE51L,0805,muRata,RoHS"
C11 C13 C26 C27 C28 C29: library part 1.02.01.0032, "GRM188R71H104KA93D,104,±10%,50V,X7R,0603,muRata,RoHS"
C14 C15 C16 C17 C19 C23: library part 02.01.00015, "C1608X7R1H104KT000N,0603,TDK,0.1uF,X7R,±10%,50V,"
C18: library part 1.02.01.0080, "GRM188R61A475KE15D,4.7uF,±10%,10V,X5R,0603,muRata,RoHS"
C20 C21: library part 1.02.17.0094, "GRM1555C1H6R2CA01D 6.2pF,±0.25PF,50V,C0G,0402,muRata,RoHS"
C22 C25: library part 02.01.00106, "GRM1885C1H180JA01D,0603,MURATA,15pF,COG,±5%,50V,"
C24: library part 02.01.00365, "CGA3E1X7R1C105KT0Y0N,1uF,±10%,16V,X7R,0603,TDK,"
D1: library part 1.04.03.0003, "SMBJ6.5CA,DO-214AA,君耀,RoHS"
D2: library part 1.04.07.0014, "MBR0520LT1G,SOD-123,ON,RoHS"
D3: library part 1.04.07.0010, "BAV99,SOT-23,NXP,RoHS"
D4: library part 04.03.00033, "BZX384-C5V1,SOD-323,NEXPERIA,"
D5: library part 1.04.07.0027, "1N4148,SOD-323,长电,RoHS"
D6: library part 1.04.07.0027, "1N4148,SOD-323,RoHS"
HOLE1 HOLE2 HOLE3 HOLE4 HOLE5 HOLE6: library part "HOLE - 不上螺丝"
J1: library part 20.02.00033, "ST-USB-002B-1,SMT,SUNGTECH,MicroUSB-A"
J2: library part 1.10.06.0010, "2.5-3T,180°,PA46本色,WF2501-WSH03T02,WCON,RoHS"
J3 J4 J9 J10 J11 J12 J13 J14 J15 J16: library part 1.10.06.0009, "2.5-2T,180°,PA46本色,WF2501-WSH02T02,WCON,RoHS"
J5 J20 J24: library part CON3, "Connector"
J6 J8: "Connector"
J7: library part CON5, "Connector"
J17 J18 J19 J21 J22: library part CON2, "Connector"
J28: library part 1.10.01.0133, "0.5FFC-24PIN,SMD,*,RoHS"
J29: library part 1.10.06.0027, "2EDGR/2EDGK-5.08-02P-14-00AH,DEGSON,RoHS"
L1: library part 1.03.01.0347, "MPH252012C2R2MT,2.2μH,±20%,700mA,1008,Sunlord,RoHs"
LED1: library part 1.04.05.0008, "0603QRC,红色,0603,创光,RoHS"
LED2 LED3 LED4 LED5: library part 1.04.05.0002, "0805QGC,绿色,0805,RoHS"
LED6 LED7: library part 1.04.05.0002, "绿色,0805,0805,RoHS"
Q1: library part 1.04.09.0002, "SS8550LT(1.5A),SOT-23,江苏长电,RoHS"
Q2 Q3 Q4 Q5: library part 1.04.09.0001, "SS8050LT(1.5A),SOT-23,长电,RoHS"
Q6: library part 1.04.09.0002, "PNP Transistor"
R1: library part 1.01.03.0019, "1MΩ,1206,RoHS"
R2: library part 1.01.01.0056, "20KΩ,0603,*,RoHS"
R3 R19 R20 R21 R24 R25 R26 R27 R28: library part 1.01.01.0038, "2KΩ,0603,*,RoHS"
R4: library part 1.01.01.0054, "15KΩ,0603,*,RoHS"
R5: library part 1.01.01.0064, "120KΩ,±1%,0603,*,RoHS"
R6: library part 1.01.01.0058, "30KΩ,0603,*,RoHS"
R7 R11 R29 R30 R31 R32 R33 R34 R35 R36: library part 1.01.01.0062, "100KΩ,0603,*,RoHS"
R8 R9: library part 1.01.01.0152, "22K,±1%,0603,RoHS"
R10: library part 1.01.01.0032, "470Ω,0603,*,RoHS"
R12 R13 R15 R37 R38 R39 R40 R49 R50 R51 R52 R53 R54 R55 R56 R57: library part 1.01.01.0001, "0Ω,0603,*,RoHS"
R14 R17 R18 R22 R23 R41 R45 R46: library part 1.01.01.0052, "10KΩ,±1%,0603,*,RoHS"
R16: library part 01.01.00021, "RTT031001DTP,0603,RALEC,1KΩ,±0.5%,1/10W"
R42 R43 R44: library part 1.01.01.0037, "1.5KΩ,0603,*,RoHS"
R47: library part 1.01.10.0003, "20Ω,±5%,2W,Ф5.5×16mm,RoHS"
R48: library part 1.01.01.0045, "4.7KΩ,0603,*,RoHS"
S1: library part 1.09.01.0003, "TS0641-0501B,6×6×5.0mm,黑色,SMD,卷带装,RoHS"
S2: library part 1.09.01.0003, "6×6×5.0mm,黑色,SMD,,*"
T1 T2 T3 T4 T5 T6: library part TEST-DOT
U1: library part 08.09.03069, "ZL6205A33TS5,SOT-23-5,ZLG"
U2: library part 1.05.09.0258, "MP1541DJ,TSOT23-5,MPS,RoHS"
U3: library part 78.59.00018
U4: library part 1.10.17.0012
U5: library part 1.10.02.0001, "DIP-8,300mil,,*"
U6: library part 1.05.10.0716, "HEF4051BTT,TSSOP16,Nexperia"
U7: library part 1.05.10.0602, "LM75BD,SO-9,NXP,RoHS"
X1: library part 1.07.01.0032, "JYD3A1C7G6-10-12.000,12.0000MHz,±10ppm,10pF,-40~85℃,±10ppm,SMD3225,*,JYEG,RoHS"
X2: library part 1.07.01.0071, "SC-20S,32.768kHz,12.5pF,±20ppm,SMD2012,SII"

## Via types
v1: diameter 0.508, hole 0.305, Top Layer to Bottom Layer, tented both sides, 599 vias

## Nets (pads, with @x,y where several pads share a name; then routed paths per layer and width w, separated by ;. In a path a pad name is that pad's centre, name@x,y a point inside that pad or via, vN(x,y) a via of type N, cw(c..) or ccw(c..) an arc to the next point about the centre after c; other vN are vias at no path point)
3.3V: C4.2 C5.2 C14.1 C15.1 C16.1 C17.1 C18.1 D5.2 J5.3 J7.1 J23.26 J24.3 J25.1 J26.24 J27.23 R3.2 R14.2 R16.2 R49.1 R53.1 R55.1 R57.1 T1.1 U1.5 U3.22 U3.30 U3.41 U3.54 | length 412
  Top Layer w0.254: 34.143,106.34 U3.22@34.143,107.152 ; 38.143,106.262 U3.30@38.143,107.152 ; U3.54@39.143,116.252 39.143,117.107 ; U3.41@40.69,110.702 41.58,110.702 ; C5.2@110.207,128.924 110.212,128.928 T1.1@111.815,128.928
  Top Layer w0.381: 106.143,129.178 R3.2@106.143,130.956
  Top Layer w0.508: C15.1@33.896,104.504 33.896,106.092 34.143,106.34 ; C15.1@34.277,104.257 34.51,104.257 C15.1@34.515,104.252 ; C16.1@36.346,104.675 C16.1@35.923,104.252 36.125,104.252 38.135,106.262 ; 39.143,117.107 v1(39.599,117.562) 40.671,118.634 C17.1@40.671,118.862 ; 41.58,110.702 v1(43.441,112.563) 43.974,113.096 C14.1@44.434,113.096 ; R14.2@45.974,111.332 v1(46.843,111.332) 47.245,111.332 D5.2@47.676,111.762 ; v1(59.067,121.149) R16.2@59.067,122.114 ; R53.1@110.232,107.254 v1(111.299,107.254)
  Top Layer w0.762: v1(31.248,103.487) 32.018,104.257 C18.1@32.499,104.257 C15.1@34.277,104.257 ; R57.1@32.35,127.978 27.311,127.978 ; C15.1@34.515,104.252 C16.1@35.923,104.252 ; J27.23@44.37,79.95 43.1,81.22 43.1,84.387 41.101,86.385 35.1,86.385 27.311,94.175 v1(27.311,103.454) 27.311,127.978 ; J26.24@44.37,148.466 45.996,150.092 47.981,150.092 48.76,149.313 48.76,144.742 v1(50.057,143.445) 59.479,143.445 60.825,144.792 60.825,148.408 62.103,149.686 84.017,149.686 J25.1@86.153,147.55 84.883,146.28 84.883,144.042 77.18,136.338 J5.3@68.271,136.338 ; v1(53.879,136.499) v1(53.32,137.058) 28.631,137.058 27.311,135.737 27.311,127.978 ; J24.3@68.271,113.478 68.544,113.478 v1(71.803,116.738) v1(72.362,117.297)
  Top Layer w1.524: R49.1@97.249,136.798 98.4,135.647 98.4,130.649 v1(98.905,130.144) v1(99.413,129.636) 99.902,129.147 C5.2@109.978,129.147
  Bottom Layer w0.508: v1(27.285,120.675) 34.211,120.675 35.862,119.024 39.985,119.024 ; v1(39.599,117.562) 39.985,117.949 v1(39.985,118.008) 39.985,119.024 ; v1(46.843,111.332) 44.671,111.332 v1(43.441,112.563) 43.441,114.656 44.295,115.511 44.295,118.186 43.457,119.024 39.985,119.024 ; v1(53.879,136.499) 56.165,136.499 58.045,134.62 58.045,128.799 59.067,127.777 v1(59.067,121.149) ; v1(107.338,129.311) v1(107.338,128.702) 107.338,128.27 112.062,123.545 112.062,111.099 111.299,110.336 v1(111.299,107.254)
  Bottom Layer w0.762: J7.1@8.755,97.506 11.665,97.506 17.646,103.487 v1(31.248,103.487) ; J27.23@44.37,79.95 45.86,78.46 48.334,78.46 49.883,80.01 49.883,84.658 51.788,86.563 60.145,86.563 J23.26@65.452,81.256 ; v1@49.574,143.929 v1(50.057,143.445) 50.057,140.321 v1(53.32,137.058) v1(53.879,136.499) ; J5.3@68.271,136.338 72.362,132.248 v1(72.362,117.297) v1(71.803,116.738)
  Bottom Layer w1.016: v1@77.163,136.338 v1(77.705,136.88) 85.57,136.88 92.307,130.144 v1(98.905,130.144) v1(99.413,129.636)
  other v1: 77.163,136.322 49.561,143.916
3.3V_PERIPHERAL: C30.1 LED6.1 LED7.1 Q6.2 R41.2 R45.2 R46.2 R48.2 R57.2 U7.8 | length 94.4
  Top Layer w0.508: R57.2@33.874,127.978 C30.1@33.874,126.124 v1(34.864,126.124) U7.8@36.235,126.124 ; R45.2@46.092,126.124 v1(47.107,126.124) ; R46.2@46.092,127.75 v1(47.107,127.75) 49.615,127.75 52.897,131.032 v1(56.648,131.032) 57.574,131.958 R48.2@57.73,131.958 ; v1(70.35,110.832) 71.537,110.832 LED6.1@74.172,113.467 LED7.1@76.712,113.467 79.354,110.824 85.954,110.824 91.843,116.713 R41.2@91.843,119.483 92.031,119.295 Q6.2@93.392,119.295
  Bottom Layer w0.508: v1(34.864,126.124) v1(47.107,126.124) v1(47.107,127.75) ; v1(56.648,131.032) 56.648,127.531 57.738,126.441 57.738,120.394 58.434,119.698 58.434,113.291 60.893,110.832 v1(70.35,110.832)
3V3_4051: R31.2 R32.2 R35.2 R36.2 R55.2 | length 22.6
  Top Layer w0.508: v1(98.753,110.175) R35.2@99.615,110.175 ; v1(98.753,114.112) R32.2@99.615,114.112 ; v1(98.753,118.176) R31.2@99.615,118.176 ; v1(98.753,122.494) R36.2@99.615,122.494 ; v1(99.876,127.654) R55.2@101.063,127.654
  Bottom Layer w0.508: v1(98.753,110.175) v1(98.753,114.112) v1(98.753,118.176) v1(98.753,122.494) 98.753,126.531 v1(99.876,127.654)
5.0V_AWORKS: C2.2 C3.2 D1.1 J1.1 J5.1 J24.1 J25.2 J26.26 J27.25 J29.1 R2.1 R54.1 R56.1 U1.1 | length 226.3
  Top Layer w0.381: R2.1@101.063,134.385 101.063,135.274 101.419,135.629 104.162,135.629 D1.1@105.965,137.433
  Top Layer w0.762: J24.1@63.191,113.478 66.753,109.917 v1(88.711,109.917) v1(89.393,109.917) ; v1(97.274,107.708) v1(97.732,108.165) 98.24,108.673 103.982,108.673 R54.1@105.332,110.023
  Top Layer w1.016: v1(53.435,109.819) 53.943,110.327 v1(53.955,110.327) 53.955,110.34 57.094,113.478 J24.1@63.191,113.478 ; R56.1@59.229,136.338 v1(60.305,136.338) J5.1@63.191,136.338
  Top Layer w1.524: D1.1@105.965,137.433 C2.2@110.131,137.433 ; D1.1@105.998,137.941 D1.1@105.998,138.137 ; J29.1@107.569,143.194 J29.1@107.569,143.206
  Bottom Layer w0.762: v1(88.711,109.917) v1(89.393,109.917) 91.602,107.708 v1(97.274,107.708) v1(97.732,108.165)
  Bottom Layer w1.016: J27.25@46.91,79.95 48.824,81.865 48.824,94.706 53.435,99.316 53.435,109.807 v1(53.955,110.327) ; J26.26@46.91,148.466 47.703,148.466 53.076,143.093 60.305,143.093 ; J24.1@63.191,113.478 62.615,113.478 61.042,115.052 61.042,128.768 60.305,129.504 v1(60.305,136.338) 60.305,143.093 ; J25.2@86.153,145.01 87.274,145.01 88.05,145.786 88.05,149.748 ; v1(110.478,136.566) 97.855,136.566 96.385,138.035 96.385,147.864 94.502,149.748 88.05,149.748 ; 60.305,143.093 60.305,147.937 62.117,149.748 88.05,149.748
  other v1: 109.746,136.562
5V/3.3VA: J23.27 J24.2 | length 49.9
  Top Layer w0.762: J23.27@65.452,78.716 70.163,78.716 76.853,85.406 v1(76.853,99.126) v1(76.853,99.808)
  Bottom Layer w0.762: J24.2@65.731,113.478 67.206,112.004 71.245,112.004 76.853,106.396 v1(76.853,99.808) v1(76.853,99.126)
5V_4051: R38.1 R54.2 | length 1.5
  Top Layer w0.508: R54.2@107.071,110.019 R38.1@108.595,110.019
5V_PERIPHERAL: R47.1 R56.2 | length 11.1
  Top Layer w0.508: R47.1@47.783,133.417 54.746,133.417 R56.2@57.667,136.338
8V: R37.1 R50.2 T3.1 | length 55
  Top Layer w0.508: T3.1@91.775,148.703 91.775,146.925 R50.2@91.801,146.9 ; v1(110.119,108.992) R37.1@110.119,110.019
  Bottom Layer w0.762: v1(90.785,147.713) v1(90.785,147.027) v1(90.785,146.341) 90.785,135.812 92.913,133.684 100.618,133.684 111.173,123.129 111.173,111.633 110.119,110.579 v1(110.119,108.992)
-5V: R39.1 R51.2 T4.1 | length 14.9
  Top Layer w0.508: R51.2@96.614,124.065 T4.1@98.067,125.518 98.57,126.021 108.52,126.021 109.394,125.147 R39.1@109.394,124.174
-5V_IN: D2.1 L1.2 R52.1 U2.1 | length 14.7
  Top Layer w0.508: L1.2@90.858,142.358 L1.2@91.142,142.074
  Top Layer w0.762: R52.1@89.455,130.954 88.033,132.376 88.033,141.52 88.871,142.358 L1.2@90.858,142.358
ADC0_AWORKS: J23.17 J26.12 J27.20 U3.50 | length 117.9
  Top Layer w0.152: U3.50@40.69,115.202 41.122,115.202 43.282,117.363 v1(48.678,117.363) ; v1(51.553,100.86) 53.687,102.994 66.574,102.994 J23.17@67.992,101.576
  Bottom Layer w0.152: J26.12@29.13,148.466 30.435,147.162 30.435,144.903 35.71,139.628 46.175,139.628 50.444,135.358 50.444,125.92 48.681,124.157 48.681,113.801 49.133,113.35 52.119,113.35 52.768,112.701 52.768,111.893 51.553,110.678 v1(51.553,100.86) 50.808,100.86 39.29,89.342 J27.20@39.29,82.49
ADC1_AWORKS: J23.16 J26.11 J27.19 U3.51 | length 159.8
  Top Layer w0.152: J26.11@29.13,145.926 26.733,143.529 23.919,143.529 19.716,139.326 19.716,118.006 v1(22.363,115.36) 24.339,113.383 24.339,94.41 34.101,84.648 39.02,84.648 40.544,83.124 40.544,81.204 J27.19@39.29,79.95 40.9,78.341 47.732,78.341 48.791,79.4 48.791,83.871 51.343,86.422 61.435,86.422 62.654,85.203 68.09,85.203 70.532,87.645 J23.16@70.532,101.576 ; U3.51@40.69,115.702 40.953,115.702 42.132,116.881 v1(42.132,117.287)
  Bottom Layer w0.152: v1(22.363,115.36) 23.103,115.36 23.574,115.831 33.734,115.831 34.156,116.252 41.097,116.252 v1(42.132,117.287)
ADC2_AWORKS: J25.5 J27.5 J27.18 J28.10 U3.38 | length 171.5
  Top Layer w0.152: J28.10@12.575,110.816 14.351,110.816 v1(15.339,109.827) 15.339,88.009 20.275,83.073 20.275,81.676 21.51,80.441 J27.5@21.51,79.95 22.807,78.654 35.007,78.654 35.464,79.111 35.464,81.204 J27.18@36.75,82.49 ; v1(25.863,109.202) 25.863,116.999 23.831,119.031 23.831,136.515 25.507,138.191 53.615,138.191 54.018,138.594 73.923,138.594 79.804,144.475 79.804,146.281 J25.5@81.073,147.55 ; v1(39.934,109.202) U3.38@40.69,109.202
  Bottom Layer w0.152: v1(15.339,109.827) 16.748,108.419 24.641,108.419 25.425,109.202 v1(25.863,109.202) v1(39.934,109.202)
ADC3_AWORKS: J25.6 J27.4 J27.17 J28.11 U3.39 | length 168.3
  Top Layer w0.152: J28.11@12.575,110.316 v1(14.144,110.316) 14.89,109.569 14.89,87.721 18.97,83.641 J27.4@18.97,82.49 18.97,82.067 20.224,80.813 20.224,79.214 21.089,78.349 35.148,78.349 J27.17@36.75,79.95 ; v1(26.371,109.702) 26.371,117.101 24.212,119.26 24.212,136.235 25.787,137.81 53.844,137.81 54.246,138.213 74.276,138.213 J25.6@81.073,145.01 ; v1(39.444,109.702) U3.39@40.69,109.702
  Bottom Layer w0.152: v1(14.144,110.316) 15.545,110.316 17.111,108.749 24.337,108.749 25.29,109.702 v1(26.371,109.702) v1(39.444,109.702)
AGND: J23.18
